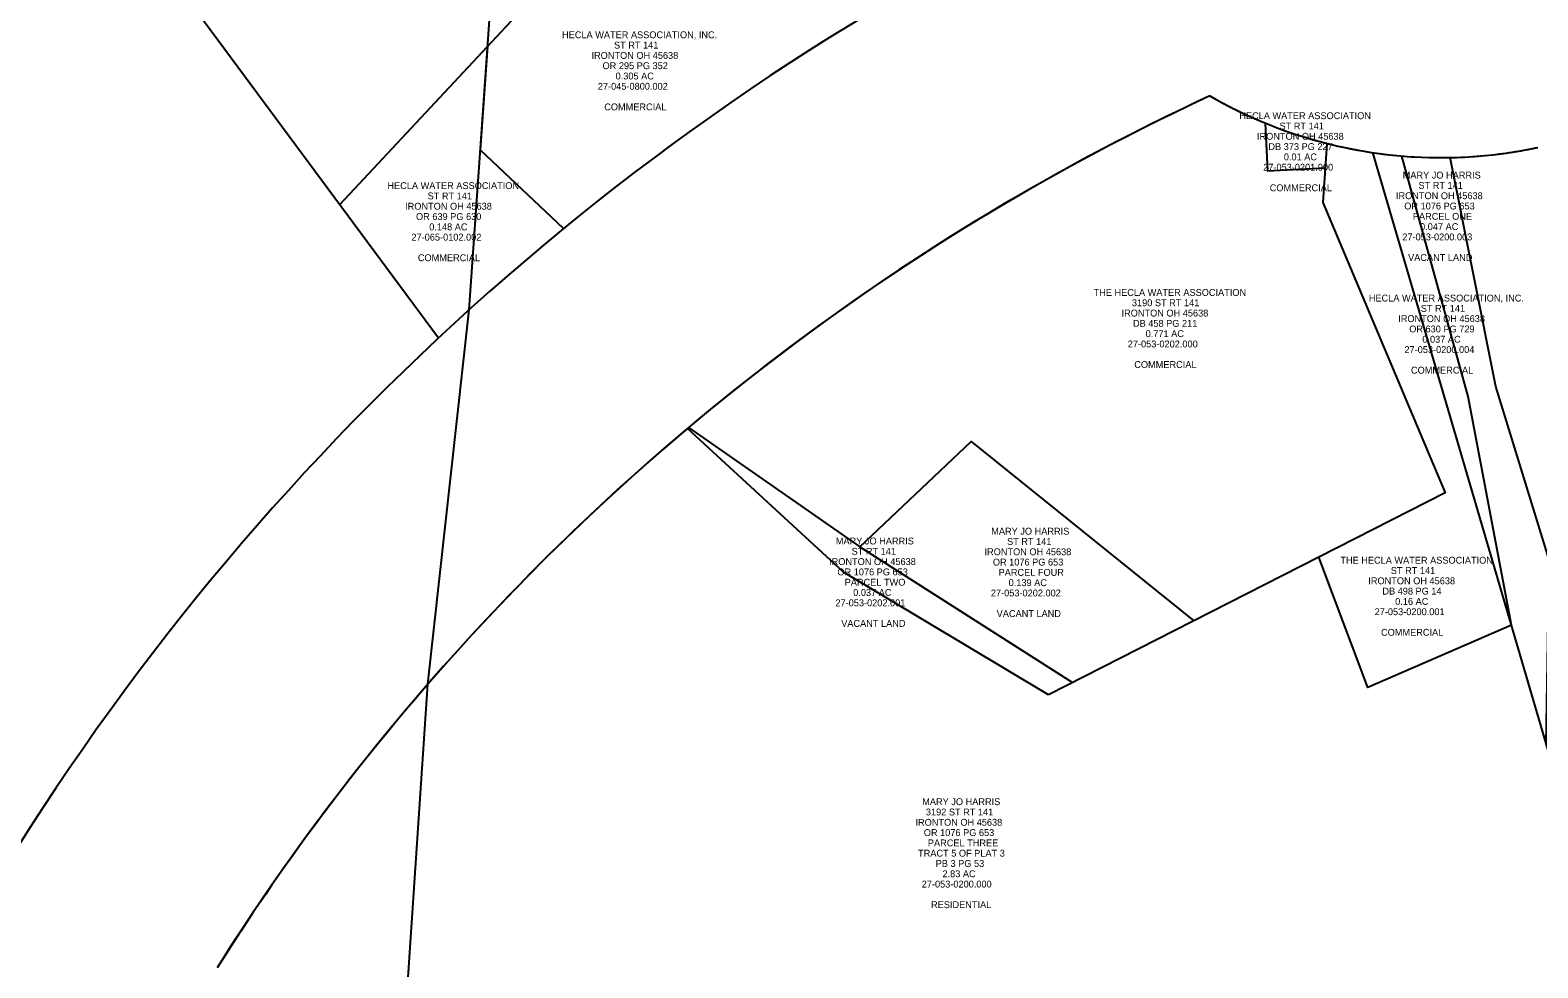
# Model space of a CAD drawing. Extents: x 1926695 to 1928303, y 198652 to 200926.
# Drawn here: x 1927197 to 1927812, y 199359 to 199742 of the extents above; entities that cross this region are included whole.
import ezdxf

# ---------------------------------------------------------------- set-up
doc = ezdxf.new("R2010")
doc.units = 0
for name, color, linetype in [('DV_X_Property_Line', 7, 'Continuous'), ('DV_X_Section_VMS_Line', 7, 'Continuous'), ('DV_X_Text', 7, 'Continuous'), ('RW_X_Fee_RW', 7, 'Continuous')]:
    doc.layers.add(name, color=color, linetype=linetype)

msp = doc.modelspace()

# ---------------------------------------------------------------- linework, layer by layer
at = {"layer": 'DV_X_Property_Line'}
for p, q in [((1927192.02, 199848.17), (1927363.59, 199616.33)), ((1927450.16, 199806.6), (1927323.3, 199670.77)), ((1927840.82, 199363.33), (1927744.59, 199691.92)), ((1927311.41, 198760.16), (1927359.21, 199475.1))]:
    msp.add_line(p, q, dxfattribs=at)
for points in [[(1927414.58, 199660.96), (1927380.67, 199692.95), (1927383.66, 199735.39)], [(1927700.67, 199703.97), (1927701.63, 199684.54), (1927725.1, 199685.69)], [(1927725.79, 199695.49), (1927724.11, 199671.59), (1927774.1, 199553.18), (1927612.29, 199470.78)], [(1927801.03, 199499.21), (1927783.38, 199592.46), (1927756.43, 199690.54)], [(1927815.25, 199450.63), (1927816.4, 199525.9), (1927794.66, 199596.59), (1927776.14, 199689.91)], [(1927612.29, 199470.78), (1927528.76, 199520.87), (1927465.09, 199579.42)], [(1927465.55, 199579.8), (1927535.39, 199531.11), (1927622.14, 199475.87)], [(1927535.39, 199531.11), (1927580.79, 199574.07), (1927671.62, 199501.04)], [(1927801.03, 199499.21), (1927742.53, 199473.85), (1927722.47, 199526.91)]]:
    msp.add_lwpolyline(points, dxfattribs=at)
for centre, radius, start, end in [((1928078.57, 198850.88), 1047.43, 116.73228, 150.49325), ((1928078.57, 198850.88), 952.43, 114.86425, 127.20389), ((1927772.34, 199879.02), 189.15, 240.11485, 268.51262), ((1927772.34, 199879.02), 189.15, 268.51262, 276.39743), ((1927772.34, 199879.02), 189.15, 276.39743, 279.65224), ((1927772.34, 199879.02), 189.15, 279.65224, 282.05144), ((1928078.57, 198850.88), 952.43, 127.20389, 139.04999), ((1928078.57, 198850.88), 952.43, 139.04999, 147.7229)]:
    msp.add_arc(centre, radius, start, end, dxfattribs=at)
at = {"layer": 'DV_X_Section_VMS_Line'}
for p, q in [((1927376.1, 199627.83), (1927467.32, 200926.12)), ((1927359.21, 199475.1), (1927376.1, 199627.83)), ((1927304.21, 198652.42), (1927359.21, 199475.1))]:
    msp.add_line(p, q, dxfattribs=at)
at = {"layer": 'RW_X_Fee_RW'}
for centre, radius, start, end in [((1928078.57, 198850.88), 1047.43, 116.73228, 150.49325), ((1928078.57, 198850.88), 952.43, 114.86425, 147.7229), ((1927772.34, 199879.02), 189.15, 240.11485, 282.05144)]:
    msp.add_arc(centre, radius, start, end, dxfattribs=at)

# ---------------------------------------------------------------- texts
at = {"layer": 'DV_X_Text'}
for s, p in [('HECLA WATER ASSOCIATION, INC.', (1927413.98, 199738.56)), ('ST RT 141', (1927435.15, 199734.36)), ('IRONTON OH 45638', (1927425.98, 199730.16)), ('OR 295 PG 352', (1927430.47, 199725.96)), ('0.305 AC', (1927435.81, 199721.76)), ('27-045-0800.002', (1927428.56, 199717.56)), ('COMMERCIAL', (1927431.17, 199709.16)), ('HECLA WATER ASSOCIATION', (1927690.11, 199705.57)), ('ST RT 141', (1927706.49, 199701.37)), ('IRONTON OH 45638', (1927697.31, 199697.17)), ('DB 373 PG 227', (1927701.97, 199692.97)), ('0.01 AC', (1927708.26, 199688.77)), ('27-053-0201.000', (1927699.85, 199684.57)), ('HECLA WATER ASSOCIATION', (1927342.77, 199677.05)), ('COMMERCIAL', (1927702.51, 199676.17)), ('MARY JO HARRIS', (1927756.73, 199681.34)), ('ST RT 141', (1927763.16, 199677.14)), ('ST RT 141', (1927359.16, 199672.85)), ('IRONTON OH 45638', (1927753.98, 199672.94)), ('IRONTON OH 45638', (1927349.98, 199668.65)), ('OR 639 PG 630', (1927354.43, 199664.45)), ('OR 1076 PG 653', (1927757.37, 199668.74)), ('PARCEL ONE', (1927760.87, 199664.54)), ('0.148 AC', (1927359.81, 199660.25)), ('0.047 AC', (1927763.81, 199660.34)), ('27-065-0102.002', (1927352.56, 199656.05)), ('27-053-0200.003', (1927756.58, 199656.14)), ('COMMERCIAL', (1927355.18, 199647.65)), ('VACANT LAND', (1927758.93, 199647.74)), ('THE HECLA WATER ASSOCIATION', (1927630.69, 199633.49)), ('3190 ST RT 141', (1927646.33, 199629.29)), ('HECLA WATER ASSOCIATION, INC.', (1927742.92, 199631.21)), ('ST RT 141', (1927764.09, 199627.01)), ('IRONTON OH 45638', (1927642.09, 199625.09)), ('DB 458 PG 211', (1927646.76, 199620.89)), ('IRONTON OH 45638', (1927754.91, 199622.81)), ('0.771 AC', (1927651.92, 199616.69)), ('OR 630 PG 729', (1927759.39, 199618.61)), ('0.037 AC', (1927764.74, 199614.41)), ('27-053-0202.000', (1927644.63, 199612.49)), ('27-053-0200.004', (1927757.43, 199610.21)), ('COMMERCIAL', (1927647.29, 199604.09)), ('COMMERCIAL', (1927760.11, 199601.81)), ('MARY JO HARRIS', (1927588.97, 199536.15)), ('MARY JO HARRIS', (1927525.6, 199532.14)), ('ST RT 141', (1927595.4, 199531.95)), ('IRONTON OH 45638', (1927522.85, 199523.74)), ('ST RT 141', (1927532.03, 199527.94)), ('IRONTON OH 45638', (1927586.23, 199527.75)), ('OR 1076 PG 653', (1927589.62, 199523.55)), ('THE HECLA WATER ASSOCIATION', (1927731.31, 199524.31)), ('OR 1076 PG 653', (1927526.24, 199519.54)), ('PARCEL FOUR', (1927591.97, 199519.35)), ('IRONTON OH 45638', (1927742.71, 199515.91)), ('ST RT 141', (1927751.88, 199520.11)), ('PARCEL TWO', (1927529.22, 199515.34)), ('0.037 AC', (1927532.68, 199511.14)), ('27-053-0202.002', (1927588.81, 199510.95)), ('0.139 AC', (1927596.06, 199515.15)), ('DB 498 PG 14', (1927748.44, 199511.71)), ('27-053-0202.001', (1927525.43, 199506.94)), ('0.16 AC', (1927753.66, 199507.51)), ('VACANT LAND', (1927527.8, 199498.54)), ('VACANT LAND', (1927591.18, 199502.55)), ('27-053-0200.001', (1927745.29, 199503.31)), ('COMMERCIAL', (1927747.9, 199494.91)), ('MARY JO HARRIS', (1927560.83, 199425.84)), ('3192 ST RT 141', (1927562.32, 199421.64)), ('IRONTON OH 45638', (1927558.08, 199417.44)), ('OR 1076 PG 653', (1927561.47, 199413.24)), ('PARCEL THREE', (1927563.13, 199409.04)), ('TRACT 5 OF PLAT 3', (1927559.14, 199404.84)), ('PB 3 PG 53', (1927566.34, 199400.64)), ('2.83 AC', (1927569.08, 199396.44)), ('27-053-0200.000', (1927560.62, 199392.24)), ('RESIDENTIAL', (1927564.43, 199383.84))]:
    msp.add_text(s, height=2.8, dxfattribs=at).set_placement(p)

doc.saveas('drawing.dxf')
